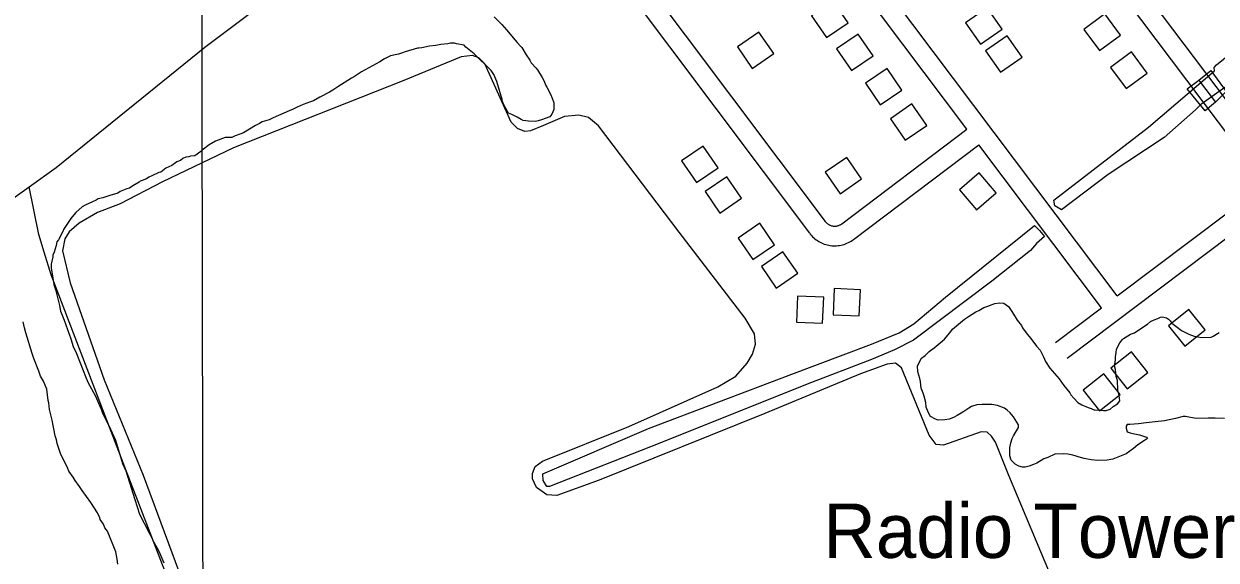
# Model space of a CAD drawing. Extents: x 3329297 to 3367176, y 649250 to 674653.
# Drawn here: x 3343648 to 3345468, y 670634 to 671453 of the extents above; entities that cross this region are included whole.
import ezdxf

# ---------------------------------------------------------------- set-up
doc = ezdxf.new("R2010")
doc.units = 0
for name, color, linetype in [('V-BLDG-OTLN', 7, 'Continuous'), ('V-BRDG-OTLN', 7, 'Continuous'), ('V-DTCH-CNTR', 7, 'Continuous'), ('V-GRID-MAJR', 7, 'Continuous'), ('V-ROAD-CNTR', 7, 'Continuous'), ('V-SITE-VEGE', 7, 'Continuous'), ('V-TOPO-SHOR', 7, 'Continuous'), ('V-TOPO-TOWR-IDEN', 7, 'Continuous')]:
    doc.layers.add(name, color=color, linetype=linetype)

msp = doc.modelspace()

# ---------------------------------------------------------------- linework, layer by layer
at = {"layer": 'V-BLDG-OTLN'}
for points in [[(3344873.0342164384, 671431.99510921), (3344906.042150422, 671454.5870640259), (3344883.449195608, 671487.595998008), (3344850.4412616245, 671465.0030431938)], [(3345108.398745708, 671421.686129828), (3345141.1286802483, 671444.6800838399), (3345118.135726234, 671477.4100183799), (3345085.404791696, 671454.4170643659)], [(3345321.9173186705, 671435.7211017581), (3345298.093366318, 671467.851037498), (3345265.96243058, 671444.0270851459), (3345289.7863829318, 671411.8961494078)], [(3344759.5644433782, 671384.703203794), (3344792.5723773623, 671407.2951586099), (3344769.9794225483, 671440.304092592), (3344736.9714885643, 671417.7111377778)], [(3344911.132140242, 671381.5852100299), (3344944.1400742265, 671404.177164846), (3344921.547119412, 671437.1860988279), (3344888.539185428, 671414.5931440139)], [(3345138.9136846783, 671378.8782154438), (3345171.643619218, 671401.872169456), (3345148.650665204, 671434.6021039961), (3345115.919730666, 671411.609149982)], [(3345362.7502370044, 671377.683217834), (3345338.9262846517, 671409.813153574), (3345306.7953489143, 671385.989201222), (3345330.6193012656, 671353.8582654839)], [(3344955.1200522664, 671329.1493149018), (3344988.12798625, 671351.7412697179), (3344965.535031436, 671384.7502036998), (3344932.5270974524, 671362.1572488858)], [(3344993.150976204, 671274.9774232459), (3345026.158910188, 671297.569378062), (3345003.565955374, 671330.5783120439), (3344970.55802139, 671307.98535723)], [(3344651.985658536, 671243.46048628), (3344674.567613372, 671210.4445523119), (3344707.5835473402, 671233.026507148), (3344685.0015925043, 671266.0424411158)], [(3344893.731175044, 671193.3455865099), (3344926.739109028, 671215.9375413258), (3344904.146154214, 671248.9464753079), (3344871.13822023, 671226.353520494)], [(3345075.87281076, 671199.39057442), (3345101.876758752, 671168.9966352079), (3345132.270697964, 671195.0005832), (3345106.2667499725, 671225.3945224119)], [(3344687.835586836, 671196.8185795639), (3344710.417541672, 671163.8026455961), (3344743.43347564, 671186.3846004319), (3344720.8515208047, 671219.4005344)], [(3344738.2544859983, 671125.748721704), (3344760.836440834, 671092.732787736), (3344793.8523748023, 671115.3147425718), (3344771.270419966, 671148.3306765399)], [(3344773.651415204, 671082.2838086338), (3344796.23337004, 671049.267874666), (3344829.249304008, 671071.8498295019), (3344806.6673491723, 671104.86576347)], [(3344883.216196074, 671008.5389561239), (3344923.1821161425, 671006.8689594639), (3344924.8511128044, 671046.833879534), (3344884.886192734, 671048.503876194)], [(3344827.2193080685, 670997.2459787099), (3344867.185228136, 670995.5759820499), (3344868.8542247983, 671035.54090212), (3344828.8893047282, 671037.2108987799)], [(3345395.131172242, 670991.8929894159), (3345420.009122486, 670960.5710520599), (3345451.3310598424, 670985.448002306), (3345426.4541095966, 671016.7709396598)], [(3345307.378347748, 670926.849119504), (3345332.2562979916, 670895.527182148), (3345363.5782353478, 670920.4041323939), (3345338.701285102, 670951.727069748)], [(3345265.1534321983, 670893.363186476), (3345290.031382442, 670862.04124912), (3345321.353319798, 670886.9181993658), (3345296.4763695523, 670918.2411367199)]]:
    msp.add_lwpolyline(points, close=True, dxfattribs=at)
at = {"layer": 'V-BRDG-OTLN'}
msp.add_lwpolyline([(3345451.204, 671320.202), (3345423.703, 671353.306), (3345441.531, 671366.635), (3345459.949, 671381.72), (3345483.449, 671349.253), (3345466.771, 671333.291)], close=True, dxfattribs=at)
msp.add_lwpolyline([(3345441.531, 671366.635), (3345445.7090000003, 671361.103), (3345466.771, 671333.291)], dxfattribs=at)
at = {"layer": 'V-DTCH-CNTR'}
msp.add_lwpolyline([(3345220.37, 670599.063), (3345151.262, 670763.2490000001), (3345131.021, 670814.113), (3345125.1010000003, 670823.419), (3345118.508, 670829.52), (3345108.958, 670829.946), (3345051.747, 670809.462), (3345040.58, 670810.6190000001), (3345029.713, 670824.502), (3344987.588, 670927.756), (3344978.5870000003, 670934.56), (3344965.9220000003, 670933.2760000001), (3344925.187, 670918.196), (3344778.944, 670857.725), (3344526.241, 670755.7980000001), (3344461.188, 670732.629), (3344446.051, 670733.635), (3344430.519, 670744.952), (3344424.4450000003, 670758.225), (3344424.1380000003, 670766.159), (3344428.5, 670776.657), (3344439.301, 670785.019), (3344571.541, 670837.7980000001), (3344707.4420000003, 670898.665), (3344734.629, 670914.811), (3344752.139, 670934.556), (3344760.346, 670948.38), (3344764.524, 670963.637), (3344763.119, 670979.475), (3344748.68, 671003.547), (3344648.271, 671134.7440000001), (3344525.213, 671296.8470000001), (3344509.617, 671309.751), (3344495.183, 671313.165), (3344472.9990000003, 671311.515), (3344440.9620000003, 671297.566), (3344421.404, 671289.658), (3344412.708, 671288.528), (3344401.417, 671292.86), (3344391.4990000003, 671302.807), (3344351.512, 671391.841), (3344342.416, 671401.025), (3344332.744, 671404.623), (3344315.35, 671402.362), (3344227.7490000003, 671366.403), (3343967.938, 671263.409), (3343859.4960000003, 671211.55), (3343794.843, 671178.0650000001), (3343760.393, 671164.816), (3343732.416, 671148.639), (3343717.037, 671135.333), (3343710.295, 671124.743), (3343707.035, 671106.3420000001), (3343718.454, 671057.522), (3343770.259, 670909.353), (3343829.907, 670763.871), (3343900.849, 670572.742)], dxfattribs=at)
at = {"layer": 'V-GRID-MAJR'}
msp.add_spline([(3343949.253, 654651.929), (3343938.678, 660710.256), (3343928.099, 666771.667), (3343917.519, 672833.103), (3343917.514, 672836.161)], degree=3, dxfattribs=at)
at = {"layer": 'V-ROAD-CNTR'}
for points in [[(3344746.036470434, 672259.5354541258), (3345232.4934975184, 671619.6907338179), (3345542.5358774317, 671207.637557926)], [(3345316.6163292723, 671037.33089854), (3344754.7994529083, 671784.3534044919)], [(3345087.446787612, 671292.1353889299), (3344730.8235008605, 671766.3214405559)], [(3344514.5769333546, 671626.4507202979), (3344871.1812201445, 671151.0636710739)], [(3344490.585981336, 671608.4387563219), (3344847.18326814, 671133.061707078)], [(3345352.6332572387, 671509.9179533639), (3345566.49182952, 671225.6955218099)], [(3344896.446169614, 671147.5146781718), (3345087.4457876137, 671292.1353889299)], [(3344914.556133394, 671123.596726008), (3345105.47775155, 671268.159436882)], [(3345292.659377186, 671019.2729346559), (3345105.478751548, 671268.159436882)], [(3345316.6153292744, 671037.33089854), (3345542.5358774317, 671207.6365579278)], [(3345240.519481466, 670942.3990884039), (3345560.5728413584, 671183.6646058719)], [(3344870.9582205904, 671151.3536704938), (3344871.734219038, 671150.369672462), (3344872.31321788, 671149.7066737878), (3344872.9312166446, 671149.0656750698), (3344873.5762153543, 671148.457676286), (3344874.250214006, 671147.8846774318), (3344874.955212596, 671147.3416785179), (3344875.681211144, 671146.836679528), (3344876.4302096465, 671146.368680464), (3344877.206208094, 671145.9366813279), (3344878.0012065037, 671145.542682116), (3344878.80820489, 671145.191682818), (3344879.639203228, 671144.878683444), (3344880.4842015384, 671144.6066839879), (3344881.33819983, 671144.376684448), (3344882.2061980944, 671144.188684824), (3344883.0821963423, 671144.0436851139), (3344883.961194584, 671143.9426853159), (3344884.8401928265, 671143.884685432), (3344885.729191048, 671143.8706854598), (3344886.619189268, 671143.8996854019), (3344887.499187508, 671143.971685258), (3344888.375185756, 671144.087685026), (3344889.24818401, 671144.247684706), (3344890.1101822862, 671144.448684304), (3344890.961180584, 671144.692683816), (3344891.8011789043, 671144.978683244), (3344892.627177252, 671145.3066825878), (3344893.432175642, 671145.672681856), (3344894.215174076, 671146.0766810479), (3344894.9821725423, 671146.5216801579), (3344895.73317104, 671147.0076791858), (3344896.74816901, 671147.7366777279)], [(3344847.406267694, 671132.7717076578), (3344848.642265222, 671131.2057107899), (3344850.1992621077, 671129.42071436), (3344851.837258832, 671127.721717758), (3344853.5582553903, 671126.1017209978), (3344855.35825179, 671124.5687240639), (3344857.227248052, 671123.1277269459), (3344859.1692441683, 671121.7787296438), (3344861.1762401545, 671120.5267321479), (3344863.23823603, 671119.376734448), (3344865.3552317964, 671118.3287365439), (3344867.5282274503, 671117.3837384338), (3344869.737223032, 671116.5507401), (3344871.986218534, 671115.8247415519), (3344874.2702139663, 671115.2127427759), (3344876.5782093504, 671114.7127437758), (3344878.906204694, 671114.327744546), (3344881.2551999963, 671114.0547450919), (3344883.620195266, 671113.9007454), (3344885.979190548, 671113.8627454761), (3344888.337185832, 671113.939745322), (3344890.695181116, 671114.1337449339), (3344893.041176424, 671114.443744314), (3344895.364171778, 671114.8677434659), (3344897.6661671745, 671115.406742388), (3344899.9391626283, 671116.0587410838), (3344902.1751581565, 671116.82073956), (3344904.3691537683, 671117.6907378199), (3344906.522149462, 671118.668735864), (3344908.627145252, 671119.7547336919), (3344910.6701411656, 671120.9397313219), (3344912.647137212, 671122.2197287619), (3344914.254133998, 671123.3747264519)], [(3345222.461517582, 670966.3550404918), (3345292.659377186, 671019.2719346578)]]:
    msp.add_lwpolyline(points, dxfattribs=at)
at = {"layer": 'V-SITE-VEGE'}
for points in [[(3344365.61, 671463.476), (3344377.419, 671451.926), (3344384.519, 671443.439), (3344397.9250000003, 671428.013), (3344401.083, 671424.155), (3344405.8140000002, 671418.756), (3344408.176, 671416.446), (3344414.525, 671405.6140000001), (3344420.068, 671397.111), (3344422.448, 671393.2440000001), (3344429.54, 671385.536), (3344431.91, 671382.447), (3344439.045, 671370.8470000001), (3344441.433, 671366.2000000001), (3344444.632, 671358.449), (3344446.215, 671356.13), (3344451.786, 671345.29), (3344454.19, 671339.085), (3344456.603, 671332.105), (3344456.717, 671321.984), (3344453.678, 671314.943), (3344452.146, 671312.59), (3344450.606, 671311.015), (3344438.201, 671306.206), (3344432.768, 671304.59), (3344428.883, 671303.769), (3344417.975, 671304.427), (3344410.181, 671305.1190000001), (3344407.049, 671306.64), (3344400.778, 671310.466), (3344392.951, 671314.273), (3344387.475, 671316.551), (3344381.1180000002, 671328.161), (3344378.711, 671334.362), (3344377.9020000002, 671337.4670000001), (3344369.815, 671364.632), (3344365.022, 671375.482), (3344361.061, 671381.667), (3344335.085, 671407.079), (3344322.5160000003, 671417.06), (3344320.147, 671420.149), (3344308.4420000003, 671422.357), (3344305.319, 671423.1), (3344299.091, 671423.032), (3344295.2060000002, 671422.209), (3344284.3170000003, 671421.312), (3344276.5470000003, 671419.67), (3344267.214, 671418.787), (3344255.561, 671416.323), (3344250.898, 671415.4940000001), (3344248.563, 671415.4670000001), (3344229.936, 671409.811), (3344224.505, 671408.1950000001), (3344219.85, 671406.587), (3344207.418, 671404.113), (3344198.127, 671399.337), (3344191.1720000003, 671394.59), (3344163.305, 671379.488), (3344152.483, 671372.361), (3344147.836, 671369.975), (3344126.9590000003, 671356.507), (3344119.227, 671351.75), (3344114.591, 671348.584), (3344099.882, 671340.635), (3344089.822, 671335.0750000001), (3344085.167, 671333.465), (3344074.311, 671329.453), (3344065.011, 671325.46), (3344058.816, 671322.275), (3344052.612, 671319.871), (3344028.589, 671309.481), (3344022.396, 671306.301), (3344011.529, 671303.0650000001), (3344007.663, 671300.687), (3344001.467, 671297.504), (3343982.9020000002, 671286.398), (3343979.028, 671284.799), (3343970.498, 671281.589), (3343965.072, 671279.193), (3343954.951, 671279.083), (3343940.22, 671273.469), (3343930.936, 671267.917), (3343920.123, 671260.012), (3343917.813, 671257.648)], [(3343917.813, 671257.648), (3343909.037, 671251.076), (3343902.035, 671250.808), (3343899.731, 671249.9400000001), (3343895.092, 671248.981), (3343890.484, 671247.2440000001), (3343886.714, 671243.982), (3343881.33, 671242.215), (3343879.054, 671240.5700000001), (3343873.758, 671236.47), (3343864.573, 671232.218), (3343857.002, 671226.4720000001), (3343853.919, 671225.572), (3343843.208, 671220.483), (3343838.6, 671218.7490000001), (3343834.799, 671216.264), (3343828.663, 671213.692), (3343825.583, 671212.791), (3343824.086, 671211.175), (3343814.182, 671205.338), (3343808.857, 671202.0160000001), (3343804.997, 671201.089), (3343795.0330000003, 671196.806), (3343791.232, 671194.322), (3343778.903, 671190.728), (3343768.133, 671187.197), (3343761.19, 671185.37), (3343758.1410000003, 671183.6950000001), (3343741.29, 671176.031), (3343736.714, 671173.5160000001), (3343726.929, 671164.569), (3343723.9390000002, 671161.335), (3343719.48, 671155.709), (3343708.44, 671138.92), (3343707.752, 671136.556), (3343700.483, 671123.029), (3343698.269, 671119.826), (3343696.924, 671114.321), (3343694.202, 671104.085), (3343692.0470000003, 671099.328), (3343692.1380000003, 671096.993), (3343689.446, 671085.981), (3343689.686, 671079.757), (3343690.6750000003, 671074.338), (3343693.7600000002, 671054.978), (3343696.455, 671045.733), (3343698.282, 671038.791), (3343702.023, 671022.573), (3343703.912, 671014.073), (3343706.486, 671007.9400000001), (3343709.12, 671000.2490000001), (3343719.568, 670971.823), (3343723.132, 670960.272), (3343728.219, 670949.559), (3343738.576, 670923.468), (3343742.049, 670914.252), (3343745.492, 670905.812), (3343757.225, 670884.449), (3343761.536, 670873.708), (3343765.788, 670864.52), (3343767.524, 670859.912), (3343780.216, 670833.911), (3343787.88, 670817.064), (3343798.597, 670781.636), (3343803.717, 670770.144), (3343817.098, 670726.248), (3343824.1950000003, 670703.924), (3343839.313, 670675.678), (3343846.106, 670661.135), (3343853.649, 670647.402), (3343861.341, 670629.7760000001)], [(3345102.382, 670871.084), (3345094.661, 670868.377), (3345090.5470000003, 670865.811), (3345082.92, 670860.699), (3345078.802, 670858.133), (3345072.307, 670854.872), (3345067.0130000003, 670851.657), (3345060.494, 670848.9990000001), (3345053.906, 670848.14), (3345043.686, 670847.747), (3345039.4080000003, 670849.388), (3345032.0330000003, 670853.318), (3345028.818, 670858.61), (3345025.465, 670867.51), (3345024.5870000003, 670874.701), (3345022.414, 670884.2490000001), (3345020.421, 670888.988), (3345017.716, 670896.711), (3345016.952, 670900.895), (3345016.72, 670906.906), (3345015.3540000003, 670911.0650000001), (3345012.557, 670921.193), (3345012.182, 670930.81), (3345018.355, 670942.486), (3345023.626, 670946.301), (3345030.008, 670952.568), (3345037.612, 670958.28), (3345046.3510000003, 670965.841), (3345053.353, 670971.528), (3345061.4220000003, 670980.871), (3345065.42, 670986.444), (3345083.498, 671001.589), (3345089.947, 671006.051), (3345101.112, 671013.105), (3345105.8510000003, 671015.093), (3345113.505, 671019.603), (3345119.444, 671021.639), (3345125.965, 671024.299), (3345130.126, 671025.6630000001), (3345137.917, 671026.568), (3345143.95, 671026.198), (3345150.772, 671021.0430000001), (3345155.2120000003, 671015.194), (3345161.0160000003, 671005.183), (3345164.207, 671000.491), (3345170.544, 670992.307), (3345172.485, 670988.77), (3345179.4930000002, 670978.809), (3345185.1580000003, 670972.405), (3345193.436, 670960.684), (3345199.1010000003, 670954.28), (3345204.305, 670944.2490000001), (3345207.59, 670937.1510000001), (3345213.994, 670927.165), (3345228.469, 670910.8690000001), (3345235.5, 670900.303), (3345244.356, 670889.207), (3345246.2770000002, 670886.27), (3345250.6920000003, 670881.023), (3345256.957, 670874.644), (3345263.109, 670871.268), (3345272.311, 670866.81), (3345277.1890000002, 670865.1900000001), (3345282.6920000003, 670862.997), (3345288.703, 670863.228), (3345295.963, 670862.304), (3345300.17, 670862.466), (3345306.111, 670864.502), (3345310.781, 670868.295), (3345317.232, 670872.757), (3345320.674, 670877.103), (3345320.5130000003, 670881.312), (3345319.7490000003, 670885.496), (3345317.6210000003, 670893.8420000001), (3345317.0640000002, 670908.27), (3345315.028, 670914.211), (3345314.008, 670925.008), (3345312.595, 670930.37), (3345314.053, 670939.457), (3345314.469, 670944.2880000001), (3345315.415, 670950.948), (3345315.8310000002, 670955.779), (3345320.8710000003, 670965.605), (3345324.8910000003, 670970.576), (3345326.626, 670972.4500000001), (3345337.2120000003, 670978.879), (3345343.153, 670980.914), (3345358.988, 670991.758), (3345363.105, 670994.327), (3345367.774, 670998.12), (3345373.091, 671000.733), (3345379.032, 671002.7660000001), (3345383.169, 671004.733), (3345386.153, 671005.449), (3345392.234, 671003.879), (3345395.332, 671001.591), (3345397.829, 670999.279), (3345400.372, 670995.764), (3345408.441, 670989.454), (3345415.2630000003, 670984.3), (3345426.3140000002, 670978.707)], [(3343791.289, 670627.851), (3343790.21, 670635.601), (3343788.234, 670646.435), (3343775.3310000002, 670677.884), (3343771.2290000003, 670683.178), (3343769.466, 670688.564), (3343764.495, 670696.164), (3343763.625, 670698.468), (3343760.215, 670706.128), (3343750.248, 670722.109), (3343737.079, 670740.301), (3343732.948, 670746.371), (3343726.364, 670755.47), (3343723.042, 670760.795), (3343716.4560000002, 670769.892), (3343714.752, 670773.7220000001), (3343703.733, 670796.672), (3343698.466, 670812.053), (3343697.477, 670817.47), (3343695.681, 670823.632), (3343690.86, 670847.6020000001), (3343687.116, 670863.8200000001), (3343685.946, 670873.904), (3343685.021, 670877.765), (3343682.803, 670894.823), (3343677.6520000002, 670907.09), (3343673.464, 670914.721), (3343670.828, 670922.409), (3343663.074, 670941.591), (3343660.441, 670949.281), (3343650.649, 670980.851), (3343648.794, 670988.5700000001), (3343646.877, 670997.845)], [(3345426.3140000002, 670978.707), (3345434.244, 670976.003), (3345445.758, 670974.039), (3345460.186, 670974.596), (3345463.146, 670975.915), (3345472.552, 670981.697)], [(3345480.642, 670850.172), (3345466.168, 670850.817), (3345455.951, 670850.422), (3345437.894, 670850.326), (3345428.809, 670851.782), (3345420.924, 670853.283), (3345417.3170000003, 670853.144), (3345405.99, 670850.299), (3345389.274, 670846.643), (3345374.895, 670844.884), (3345361.094, 670843.7490000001), (3345349.117, 670842.082), (3345335.918, 670840.97), (3345332.309, 670840.831), (3345330.599, 670838.357), (3345330.716, 670835.353), (3345332.127, 670829.991), (3345336.403, 670828.351), (3345343.086, 670826.8), (3345350.968, 670825.297), (3345361.35, 670821.486), (3345363.224, 670819.751), (3345358.532, 670816.56), (3345348.544, 670810.154), (3345341.539, 670804.4670000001), (3345330.421, 670796.211), (3345310.262, 670788.21), (3345301.292, 670786.657), (3345286.866, 670786.1), (3345277.202, 670786.932), (3345266.29, 670788.9180000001), (3345260.809, 670790.514), (3345249.2260000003, 670794.28), (3345241.341, 670795.781), (3345235.308, 670796.15), (3345221.482, 670795.615), (3345210.85, 670790.3910000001), (3345204.907, 670788.353), (3345194.319, 670781.927), (3345188.98, 670779.9130000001), (3345182.461, 670777.255), (3345176.497, 670775.819), (3345172.287, 670775.658), (3345166.808, 670777.251), (3345161.258, 670780.649), (3345155.0160000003, 670786.428), (3345152.958, 670792.969), (3345153.0700000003, 670805.618), (3345154.596, 670812.9), (3345156.744, 670819.604), (3345158.3850000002, 670823.882), (3345164.625, 670833.755), (3345166.335, 670836.229), (3345166.173, 670840.436), (3345158.473, 670852.781), (3345153.433, 670858.606), (3345149.062, 670862.653), (3345144.714, 670866.095), (3345134.333, 670869.909), (3345125.248, 670871.365), (3345110.7970000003, 670871.408), (3345102.382, 670871.084)]]:
    msp.add_lwpolyline(points, dxfattribs=at)
at = {"layer": 'V-TOPO-SHOR'}
for p, q in [((3345221.793, 671174.839), (3345220.343, 671183.482)), ((3344440.362, 670755.509), (3344439.963, 670765.837))]:
    msp.add_line(p, q, dxfattribs=at)
for points in [[(3342332.19, 670211.608), (3342475.187, 670320.574), (3342619.561, 670435.161), (3342855.327, 670614.5480000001), (3343080.457, 670780.79), (3343310.02, 670955.957), (3343491.184, 671086.2880000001), (3343655.759, 671203.905), (3343697.159, 671233.492), (3343924, 671417.308), (3344230.194, 671647.952), (3344409.202, 671782.473), (3344486.921, 671840.878), (3344733.595, 672026.254), (3344845.948, 672104.595)], [(3345465.509, 671380.844), (3345464.753, 671386.277), (3345468.571, 671390.402), (3345532.614, 671442.21), (3345545.143, 671447.4670000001), (3345560.024, 671453.613), (3345584.989, 671466.514), (3345663.913, 671524.464), (3345697.738, 671555.212), (3345729.363, 671581.099), (3345748.217, 671587.397), (3345760.134, 671587.858), (3345771.073, 671593.055), (3345778.804, 671598.9230000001), (3345791.639, 671596.236), (3345790.449, 671585.846), (3345781.343, 671574.353), (3345748.987, 671546.846), (3345683.201, 671498.9500000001)], [(3345220.343, 671183.482), (3345364.8370000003, 671294.8910000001), (3345465.509, 671380.844)], [(3345388.525, 671279.095), (3345436.204, 671321.28), (3345446.274, 671331.38), (3345481.186, 671355.889), (3345495.074, 671342.888)], [(3345388.525, 671279.095), (3345303.182, 671222.488), (3345232.049, 671168.816), (3345221.793, 671174.839)], [(3344118.404, 669978.508), (3344077.194, 670077.175), (3344009.358, 670247.226), (3343920.461, 670468.183), (3343799.307, 670782.584), (3343689.559, 671069.578), (3343678.674, 671104.169), (3343670.48, 671130.906), (3343655.759, 671203.905)], [(3344439.963, 670765.837), (3344601.2120000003, 670834.925), (3344816.09, 670916.427), (3344941.588, 670963.447), (3344983.879, 670980.9940000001), (3345006.427, 670994.595), (3345054.981, 671035.461), (3345190.798, 671144.943), (3345198.255, 671137.273), (3345205.773, 671128.0160000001), (3345193.461, 671117.196), (3345184.325, 671106.498), (3345125.66, 671059.674), (3345005.79, 670969.904)], [(3345005.79, 670969.904), (3344976.914, 670955.263), (3344941.682, 670940.3740000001), (3344843.687, 670902.376), (3344618.788, 670812.528), (3344450.264, 670746.343), (3344446.293, 670746.189), (3344440.362, 670755.509)]]:
    msp.add_lwpolyline(points, dxfattribs=at)

# ---------------------------------------------------------------- texts
at = {"layer": 'V-TOPO-TOWR-IDEN'}
msp.add_text('Radio Tower', height=82.99983200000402, dxfattribs=at).set_placement((3344868.1511931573, 670637.293228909))

doc.saveas('drawing.dxf')
